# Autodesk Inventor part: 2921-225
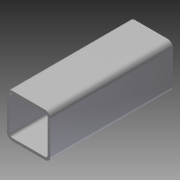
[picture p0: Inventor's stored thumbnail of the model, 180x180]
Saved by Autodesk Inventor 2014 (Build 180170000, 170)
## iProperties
Company: NHTSA/VRTC
Created: 2012-08
Part Number: 2921-225
Material: Steel, Mild
Document SubType Name: Modeling
Designer: Mike Vanvoorhis
Density: 7.86 g/cm^3
Mass: 695.306 g
Surface Area: 531.266 cm^2
Volume: 88.4614 cm^3
Project: CHILD SIDE IMPACT SLED
Description: IMPACTOR STOP MECH. TUBE
Stock Number: T.S. 2"(50.8mm) x 2"(50.8mm) x 1/8"(3.2mm) x 0'-6"(149.9mm)
Appearance: Steel
Author: Dave Walker
Title: Impactor Stop Mech. Tube
Subject: Child Side Impact Sled
Revision Number: A
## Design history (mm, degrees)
sketch "Sketch1"
  geometry: L1 (6.35, 0)-(44.45, 0); L2 (50.8, 6.35)-(50.8, 44.45); L3 (44.45, 50.8)-(6.35, 50.8); L4 (0, 44.45)-(0, 6.35); L5 (6.35, 47.625)-(44.45, 47.625); L6 (47.625, 44.45)-(47.625, 6.35); L7 (44.45, 3.175)-(6.35, 3.175); L8 (3.175, 6.35)-(3.175, 44.45); A1 r 6.35 centre (6.35, 44.45) between (6.35, 50.8) and (0, 44.45); A2 r 6.35 centre (44.45, 44.45) between (50.8, 44.45) and (44.45, 50.8); A3 r 6.35 centre (44.45, 6.35) between (44.45, 0) and (50.8, 6.35); A4 r 6.35 centre (6.35, 6.35) between (0, 6.35) and (6.35, 0); A5 r 3.175 centre (44.45, 44.45) between (47.625, 44.45) and (44.45, 47.625); A6 r 3.175 centre (44.45, 6.35) between (44.45, 3.175) and (47.625, 6.35); A7 r 3.175 centre (6.35, 6.35) between (3.175, 6.35) and (6.35, 3.175); A8 r 3.175 centre (6.35, 44.45) between (6.35, 47.625) and (3.175, 44.45); 4 further points
  constraints: 16 end point, 16 point on circle, 8 centre point, 8 point on line, 8 tangent, 4 parallel, 3 equal radius, 2 perpendicular, 1 horizontal, 7 other
  dimensions: "d0" = 50.8 distance of point (0, 50.8) point (50.8, 50.8); "d1" = 50.8 distance of point (50.8, 50.8) point (50.8, 0); "d2" = 6.35 radius of A1; "d5" = 3.175 distance between parallel lines of L8 L4
extrude "Extrusion1" new body sketch "Sketch1" distance "d3" = 142.875; taper "d4" = 0 deg
body "Solid1"
